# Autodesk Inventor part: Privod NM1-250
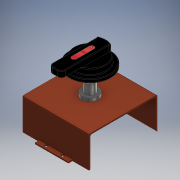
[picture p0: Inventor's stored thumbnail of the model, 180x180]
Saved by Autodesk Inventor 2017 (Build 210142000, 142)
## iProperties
Part Number: Privod NM1-250
Material: Типовые
Document SubType Name: Modeling
Designer: RSagdiev
Density: 1 g/cm^3
Appearance: По умолчанию
Author: RSagdiev
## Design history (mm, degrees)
sketch "Эскиз1"
  geometry: L1 (-26.25, 60.5)-(26.25, 60.5); L2 (26.25, 60.5)-(26.25, 52); L3 (26.25, 52)-(15.125, 52); L4 (-26.25, 52)-(-26.25, 60.5); L5 (0, 0)-(119.698, 0); L6 (0, 0)-(-104.809, 0); L7 (0, 94.88)-(0, -60.954); L8 (-15.125, 52)-(-11.125, 52); L9 (-11.125, 52)-(-11.125, 57); L10 (-13.125, 59)-(-13.125, 59); L11 (-15.125, 57)-(-15.125, 52); L12 (11.125, 52)-(11.125, 57); L13 (13.125, 59)-(13.125, 59); L14 (15.125, 52)-(11.125, 52); L15 (15.125, 57)-(15.125, 52); L16 (-15.125, 52)-(-26.25, 52); L17 (-11.125, 52)-(-15.125, 52); L18 (11.125, 52)-(-11.125, 52); L19 (15.125, 52)-(11.125, 52); A1 r 2 centre (-13.125, 57) between (-13.125, 59) and (-15.125, 57); A2 r 2 centre (-13.125, 57) between (-11.125, 57) and (-13.125, 59); A3 r 2 centre (13.125, 57) between (13.125, 59) and (11.125, 57); A4 r 2 centre (13.125, 57) between (15.125, 57) and (13.125, 59); 5 further points
  constraints: 38 end point, 10 point on line, 10 symmetric about line, 8 parallel, 8 point on circle, 4 centre point, 4 horizontal, 4 tangent, 2 perpendicular, 1 concentric, 1 midpoint, 1 vertical, 2 other
  dimensions: "d0" = 52 distance between parallel lines of L3 L6 (= 0.5 x Высота); "d1" = 8.5 distance of L1.end L2.end; "d2" = 52.5 distance between parallel lines of L2 L4 (= 0.5 x Ширина); "d3" = 4 distance of point (-15.125, 59) point (-11.125, 59); "d4" = 7 distance of point (-11.125, 59) L8.end; "d5" = 2 radius of A1 (derived); "d6" = 13.125 distance from line of L4 A1.centre (= 0.25 x d2)
extrude "Выдавливание1" new body sketch "Эскиз1" distance "d7" = 2; taper "d8" = 0 deg
mirror "Зеркальное отражение1"
sketch "Эскиз2"
  geometry: L1 (-26.25, 60.5)-(-26.25, 52) reference; L2 (26.25, 52)-(26.25, 60.5) reference; L3 (-26.25, -60.5)-(-26.25, -52) reference; L4 (26.25, -52)-(26.25, -60.5) reference; L5 (-52.5, 54)-(52.5, 54); L6 (52.5, 54)-(52.5, 52); L7 (52.5, 52)-(-52.5, 52); L8 (-52.5, 52)-(-52.5, 54); L9 (-26.25, 52)-(-15.125, 52) reference
  constraints: 8 end point, 2 parallel, 1 collinear, 1 horizontal, 1 perpendicular
  dimensions: "d13" = 105 distance of L5.start L5.end (= Ширина); "d14" = 2 distance of L5.end L6.end; "d15" = 26.25 distance between parallel lines of L1 L8 (= 0.25 x d13)
extrude "Выдавливание2" join sketch "Эскиз2" distance "d11" = 50 (computed from H1); taper "d12" = 0 deg
mirror "Зеркальное отражение2"
sketch "Эскиз3"
  geometry: L1 (-52.5, 54)-(-26.25, 54) reference; L2 (52.5, -54)-(-52.5, -54) reference; L3 (-52.5, 54)-(52.5, 54); L4 (52.5, 54)-(52.5, -54); L5 (52.5, -54)-(-52.5, -54); L6 (-52.5, -54)-(-52.5, 54); 1 further point
  constraints: 8 end point, 2 parallel, 1 horizontal, 1 perpendicular
extrude "Выдавливание3" join sketch "Эскиз3" distance "d16" = 2; taper "d17" = 0 deg
fillet "Сопряжение1" dims "d18" = 2
sketch "Эскиз4"
  geometry: L1 (52.5, -50)-(-52.5, -50) reference; L2 (52.5, -50)-(52.5, 50) reference; L3 (-52.5, 50)-(52.5, 50) reference; L4 (-52.5, 50)-(-52.5, -50) reference; L5 (-52.5, 50)-(-52.5, -50) reference; L6 (-52.5, -50)-(52.5, 50); L7 (52.5, -50)-(52.5, 50) reference; L8 (-52.5, 50)-(52.5, -50); C1 r 5 at (0, 0); 1 further point
  constraints: 4 end point, 1 centre point, 1 coincident
  dimensions: "d19" = 10 diameter of C1
extrude "Выдавливание4" cut sketch "Эскиз4" distance "d20" = 10; taper "d21" = 0 deg
sketch "Эскиз5"
  geometry: C1 r 5 at (0, 0) reference; C2 r 5 at (0, 0); C3 r 8 at (0, 0); 1 further point
  constraints: 2 centre point, 2 coincident
  dimensions: "d22" = 16 diameter of C3
extrude "Выдавливание5" new body sketch "Эскиз5" distance "d23" = 18 (= 0.333333 x H1); taper "d24" = 0 deg
sketch "Эскиз6"
  geometry: C1 r 5 at (0, 0) reference; C2 r 5 at (0, 0); 1 further point
  constraints: 1 centre point, 1 coincident
extrude "Выдавливание6" new body sketch "Эскиз6" distance "d25" = 68 (computed from H1); taper "d26" = 0 deg
sketch "Эскиз7"
  geometry: C1 r 5 at (0, 0) reference; C2 r 13 at (0, 0); C3 r 8 at (0, 0); C4 r 5 at (0, 0); 1 further point
  constraints: 3 centre point, 3 coincident
  dimensions: "d27" = 26 diameter of C2; "d28" = 16 diameter of C3; "d29" = 10 diameter of C4
extrude "Выдавливание7" new body sketch "Эскиз7" distance "d30" = 5; taper "d31" = 0 deg
extrude "Выдавливание8" join sketch "Эскиз7" distance "d32" = 20; taper "d33" = 0 deg
sketch "Эскиз8"
  geometry: C1 r 7 at (0, 0); 1 further point
  constraints: 1 centre point, 1 coincident
  dimensions: "d34" = 14 diameter of C1
extrude "Выдавливание9" new body sketch "Эскиз8" distance "d35" = 3; taper "d36" = 0 deg
fillet "Сопряжение2" dims "d37" = 3
sketch "Эскиз9"
  geometry: L1 (1, 13.17)-(-1, 13.17); L2 (-1, 13.17)-(-1, -13.17); L3 (-1, -13.17)-(1, -13.17); L4 (1, -13.17)-(1, 13.17); L5 (1, 13.17)-(-1, -13.17); L6 (-1, 13.17)-(1, -13.17); L7 (17.109, -1)-(-17.109, -1); L8 (-17.109, -1)-(-17.109, 1); L9 (-17.109, 1)-(17.109, 1); L10 (17.109, 1)-(17.109, -1); L11 (17.109, -1)-(-17.109, 1); L12 (-17.109, -1)-(17.109, 1); C1 r 4 at (0, 0) reference; C2 r 5 at (0, 0) reference; 1 further point
  constraints: 24 end point, 4 midpoint, 4 parallel, 2 horizontal, 2 perpendicular
  dimensions: "d38" = 2 distance of L3.end L2.end; "d39" = 2 distance of L7.end L8.end
extrude "Выдавливание10" cut sketch "Эскиз9" distance "d40" = 1; taper "d41" = 0 deg
sketch "Эскиз10"
  geometry: C1 r 25 at (0, 0); A1 r 4 centre (0, 0) between (1, -3.873) and (3.873, -1) reference; 1 further point
  constraints: 1 centre point, 1 coincident
  dimensions: "d42" = 50 diameter of C1
extrude "Выдавливание11" new body sketch "Эскиз10" distance "d43" = 6; taper "d44" = 0 deg; dims "d48" = 3, "d49" = 0
sketch "Эскиз11"
  geometry: C1 r 10.111 at (0, 0); C2 r 32.5 at (0, 0); 1 further point
  constraints: 2 centre point, 1 coincident
  dimensions: "d45" = 65 diameter of C2
extrude "Выдавливание12" join sketch "Эскиз11" distance "d46" = 6; taper "d47" = 0 deg
sketch "Эскиз12"
  geometry: L1 (-4, -55.108)-(4, -55.108); L2 (10, -49.108)-(10, 19.932); L3 (-10, 19.932)-(-10, -49.108); L4 (-10, -55.108)-(10, 22.913); L5 (10, -55.108)-(-10, -5.81); L6 (-12, 21.932)-(12, 21.932); A1 r 25 centre (0, 0) between (10, 22.913) and (-2.256, -24.898) reference; A2 r 25 centre (0, 0) between (10, 22.913) and (-2.256, -24.898) reference; A3 r 6 centre (-4, -49.108) between (-10, -49.108) and (-4, -55.108); A4 r 6 centre (4, -49.108) between (4, -55.108) and (10, -49.108); A5 r 2 centre (-12, 19.932) between (-10, 19.932) and (-12, 21.932); A6 r 2 centre (12, 19.932) between (12, 21.932) and (10, 19.932); A7 r 25 centre (0, 0) between (12, 21.932) and (-12, 21.932)
  constraints: 16 point on circle, 12 end point, 8 point on line, 8 tangent, 5 centre point, 2 equal radius, 2 horizontal, 1 coincident, 1 parallel, 1 perpendicular
  dimensions: "d63" = 35 distance of L4.end L5.end (computed from d76); "d64" = 6 radius of A3; "d66" = 10 distance from line of A1.centre L3; "d67" = 2 radius of A5; "d68" = 2 radius of A6 (derived); "d76" = 50 diameter of A1 (derived)
extrude "Выдавливание13" join sketch "Эскиз12" distance "d55" = 10; taper "d56" = 0 deg
fillet "Сопряжение9" dims "d69" = 1
fillet "Сопряжение10" dims "d70" = 1
sketch "Эскиз13"
  geometry: L1 (0, 2.554)-(0, -25); L2 (-4, 2.554)-(-4, -25); L3 (4, -25)-(4, 2.554); L4 (-4, -55.108)-(4, -55.108) reference; A1 r 25 centre (0, 0) between (25, 0) and (0, -25) reference; A2 r 4 centre (0, 2.554) between (4, 2.554) and (-4, 2.554); A3 r 4 centre (0, -25) between (-4, -25) and (4, -25); 2 further points
  constraints: 8 end point, 5 point on circle, 4 tangent, 2 centre point, 1 midpoint, 1 parallel, 1 vertical
  dimensions: "d71" = 8 diameter of A3; "d77" = 27.55378 distance of L1.start L1.end (= 0.5 x d78); "d78" = 55.10756 distance from line of L4 A1.centre (derived)
extrude "Выдавливание14" cut sketch "Эскиз13" distance "d72" = 0.1; taper "d73" = 0 deg
sketch "Эскиз14"
  geometry: L1 (0, 4.093)-(1.333, 1.784); L2 (1.333, 1.784)-(-1.333, 1.784); L3 (-1.333, 1.784)-(0, 4.093); L4 (0, 6.554)-(0, -31.5); L5 (4, 2.554)-(4, -25) reference; L6 (-4, -25)-(-4, 2.554) reference; A1 r 4 centre (0, 2.554) between (4, 2.554) and (-4, 2.554) reference; A2 r 4 centre (0, 2.554) between (4, 2.554) and (-4, 2.554) reference; A3 r 31.5 centre (0, 0) between (-31.5, 0) and (0, -31.5) reference; 2 further points
  constraints: 8 end point, 3 point on circle, 1 coincident, 1 point on line, 1 vertical, 7 other
  dimensions: "d79" = 8 distance between parallel lines of L5 L6 (derived); "d80" = 2.66667 distance of L1.end L2.end (= 0.333333 x d79)
extrude "Выдавливание15" join sketch "Эскиз14" distance "d74" = 0.1; taper "d75" = 0 deg
node "Твердое тело1"
node "Спроецированная петля1"
node "Твердое тело2"
node "Твердое тело3"
node "Твердое тело4"
node "Твердое тело5"
node "Спроецированная петля2"
node "Твердое тело6"
node "Спроецированная петля3"
other parameters: "H1" = 54 [user parameter; used in 3 equation terms], "Высота" = 104 [user parameter; used in 1 equation term], "Ширина" = 105 [user parameter; used in 2 equation terms]
